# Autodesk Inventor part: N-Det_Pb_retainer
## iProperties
Shininess: 64.0
Length Units: 11269
Angle Units: 11279
Time Units: 11290
Mass Units: 11283
Length Display Precision: 3
Angle Display Precision: 2
Compacted: True
Part Number: N-Det_Pb_retainer
Document SubType Name: Modeling
Created: 2005-04
Material: Steel, Mild
Designer: John Blackburn
Manufacturer: Standard
Standards Organization: Custom
Density: 0.0
Volumn: 0.0
Area: 0.0
PropertySet Name: Model Information
Control State: 0
Master: False
Checked Out: False
Author: John Blackburn
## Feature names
1. Extrusion1
2. Extrusion2
3. Chamfer1
4. Fillet1
